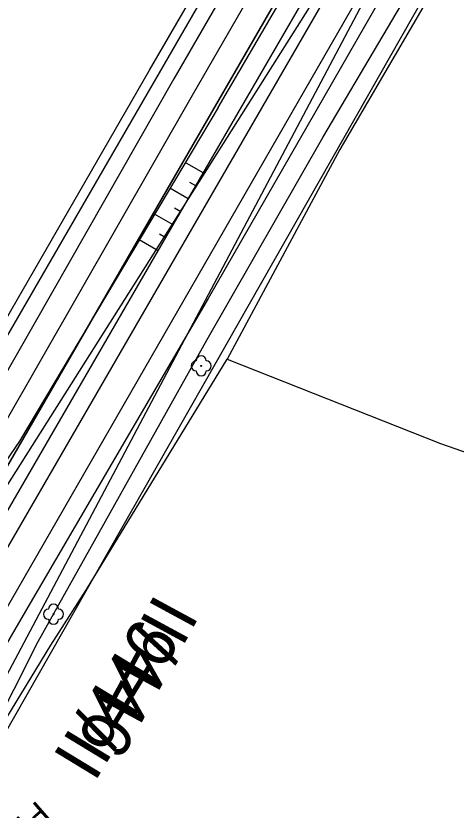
# Model space of a CAD drawing. Extents: x -555887 to -552101, y -1100251 to -1096546.
# Drawn here: x -554014.6 to -553970.5, y -1097317.8 to -1097238.2 of the extents above; entities that cross this region are included whole.
import ezdxf

# ---------------------------------------------------------------- set-up
doc = ezdxf.new("R2010")
doc.units = 0
for name, color, linetype in [('PARCELY_silnice', 7, 'Continuous'), ('POLYGONY_SITUACE_PF_POPISY', 7, 'Continuous'), ('ROZHLED_ram_legenda_1', 7, 'Continuous'), ('ROZHLED_ram_legenda_2', 7, 'Continuous'), ('ROZHLED_trojuhelniky_1', 7, 'Continuous'), ('ROZHLED_trojuhelniky_2', 7, 'Continuous'), ('ZSST', 7, 'Continuous')]:
    doc.layers.add(name, color=color, linetype=linetype)

msp = doc.modelspace()

# ---------------------------------------------------------------- linework, layer by layer
at = {"layer": 'PARCELY_silnice'}
for points in [[(-553861.3, -1097003.46), (-553858.48, -1097005.9), (-553845.75, -1096975.04), (-553836.44, -1096945.29), (-553831.55, -1096945.97), (-553834.33, -1096958.81), (-553843.04, -1096981.51), (-553856.4, -1097007.66), (-554032.65, -1097312.99), (-554038, -1097312.7), (-554039.52, -1097311.76)], [(-553831.55, -1096945.97), (-553822.14, -1096946.52), (-553820.19, -1096947.25), (-553823.19, -1096962.08), (-553832.13, -1096986.8), (-553848.04, -1097015.24), (-554028.81, -1097333.03), (-554038.74, -1097323.54), (-553856.4, -1097007.66), (-553843.04, -1096981.51), (-553834.33, -1096958.81)]]:
    msp.add_lwpolyline(points, close=True, dxfattribs=at)
at = {"layer": 'ROZHLED_trojuhelniky_1'}
for p in [(-554036.491, -1097318.429), (-554032.67, -1097321.18)]:
    msp.add_line(p, (-553972.591, -1097217.302), dxfattribs=at)
at = {"layer": 'ROZHLED_trojuhelniky_2'}
for p in [(-554030.46, -1097323.44), (-554027.516, -1097326.853)]:
    msp.add_line(p, (-553970.641, -1097219.412), dxfattribs=at)
at = {"layer": 'ZSST'}
for p, q in [((-553994.38, -1097247.36), (-553979.9, -1097222.62)), ((-553995.859, -1097253.902), (-553997.656, -1097252.862)), ((-553996.61, -1097255.201), (-553997.214, -1097254.851)), ((-553997.361, -1097256.499), (-553999.191, -1097255.44)), ((-553998.112, -1097257.797), (-553998.727, -1097257.442)), ((-553998.863, -1097259.096), (-554000.726, -1097258.018)), ((-553999.614, -1097260.394), (-554000.24, -1097260.032)), ((-554000.366, -1097261.692), (-554002.261, -1097260.596))]:
    msp.add_line(p, q, dxfattribs=at)
for points in [[(-554042.48, -1097312.42), (-554035.18, -1097301.12), (-554020.35, -1097276.71), (-554001.25, -1097243.62), (-553975.55, -1097199.35), (-553927.26, -1097115.35), (-553902.63, -1097072.54), (-553878.35, -1097029.34), (-553858.27, -1096995.26), (-553851.54, -1096982.63), (-553845.34, -1096967.24), (-553838.37, -1096941.91), (-553834.5, -1096923.22)], [(-553831.64, -1096923.82), (-553835.69, -1096943.09), (-553842.4, -1096966.86), (-553850.34, -1096985.69), (-553856.05, -1096996.17), (-553876.09, -1097031.09), (-553900.82, -1097073.95), (-553925.65, -1097117.01), (-553973.36, -1097200.46), (-553998.81, -1097244.48), (-554018.03, -1097278.18), (-554032.06, -1097302.7), (-554039.09, -1097314.61), (-554042.48, -1097312.42), (-554044.85, -1097316.43), (-554041.28, -1097318.43), (-554043.66, -1097322.75), (-554050.44, -1097334.64), (-554051.91, -1097337.2)], [(-553818.18, -1096926.71), (-553821.78, -1096945.09), (-553822.5, -1096948.29), (-553824.54, -1096956.94), (-553827.64, -1096967.4), (-553833.07, -1096981.13), (-553839.89, -1096995.89), (-553855.52, -1097024.97), (-553869.86, -1097050.06), (-553885.29, -1097076.39), (-553900.2, -1097101.88), (-553913.69, -1097125.22), (-553931.8, -1097156.33), (-553935.29, -1097162.25), (-553959.78, -1097204.54), (-553977.15, -1097234.71), (-553995.37, -1097266.5), (-554014.37, -1097299.01), (-554027.49, -1097321.67), (-554032.14, -1097329.71), (-554046.52, -1097353.89)], [(-553924.99, -1097120.68), (-553971.37, -1097201.71), (-553996.85, -1097245.92), (-554016.03, -1097279.48), (-554030.15, -1097304.02), (-554037.01, -1097315.92), (-554034.1, -1097317.54), (-554032.86, -1097317.31), (-554031.97, -1097316.4), (-554020.07, -1097295.69), (-554001.07, -1097262.91), (-553982.69, -1097231.14), (-553965.04, -1097200.55), (-553952.61, -1097179.27), (-553950.84, -1097176.19), (-553920.35, -1097123.26)], [(-553943.15, -1097184.71), (-553947.95, -1097193.13), (-553964.05, -1097220.5), (-553982.17, -1097251.56), (-553993.46, -1097272.56)], [(-554019.6, -1097315.12), (-554012.38, -1097300.85), (-553995.46, -1097270.6), (-553983.87, -1097250.35), (-553971.79, -1097229.88), (-553973.03, -1097229.25)], [(-553994.38, -1097247.36), (-554014.28, -1097280.78), (-554030.15, -1097304.02)], [(-554017.87, -1097337.24), (-554021.88, -1097329.21), (-554022.01, -1097324.3), (-554019.6, -1097315.12), (-554011.11, -1097301.23), (-554007.55, -1097295.64), (-553993.46, -1097272.56), (-553972.08, -1097281.03), (-553917.98, -1097299.93), (-553859.38, -1097321.17), (-553801.93, -1097342.05)]]:
    msp.add_lwpolyline(points, dxfattribs=at)
for centre in [(-553996.06, -1097273.24), (-554010.858, -1097298.125)]:
    msp.add_circle(centre, 0.05, dxfattribs=at)
for centre, start, end in [((-553996.56, -1097273.24), 90, 270), ((-553996.06, -1097272.74), 0, 180), ((-553995.56, -1097273.24), 270, 90), ((-553996.06, -1097273.74), 180, 0), ((-554010.858, -1097297.625), 0, 180), ((-554011.358, -1097298.125), 90, 270), ((-554010.358, -1097298.125), 270, 90), ((-554010.858, -1097298.625), 180, 0)]:
    msp.add_arc(centre, 0.5, start, end, dxfattribs=at)

# ---------------------------------------------------------------- texts
at = {"layer": 'POLYGONY_SITUACE_PF_POPISY'}
msp.add_text('PF 1', height=2.5, rotation=220.90993, dxfattribs=at).set_placement((-554012.488, -1097316.709))
at = {"layer": 'ROZHLED_ram_legenda_1'}
msp.add_text('II/446', height=5, rotation=241.51256, dxfattribs=at).set_placement((-554000.601, -1097295.884))
at = {"layer": 'ROZHLED_ram_legenda_2'}
msp.add_text('II/446', height=5, rotation=58.68547, dxfattribs=at).set_placement((-554006.766, -1097315.056))

doc.saveas('drawing.dxf')
